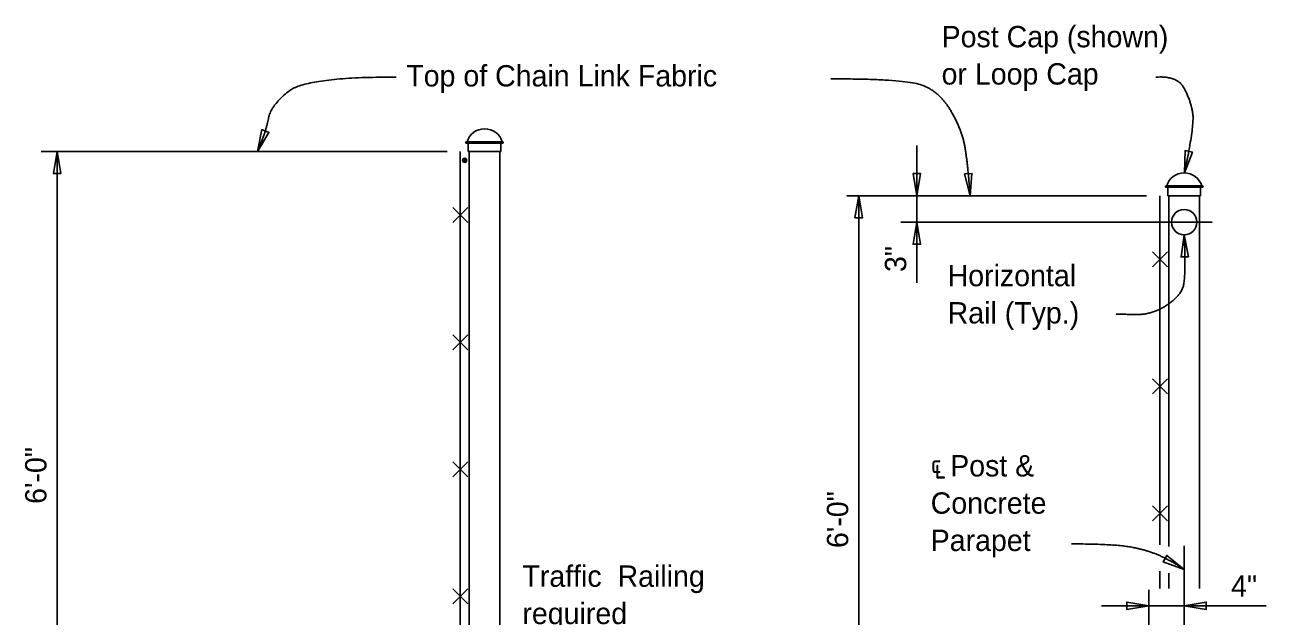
# Model space of a CAD drawing. Extents: x 0.2 to 40.8, y 0.5 to 25.7.
# Drawn here: x 29.1 to 40.83, y 18.84 to 24.42 of the extents above; entities that cross this region are included whole.
import ezdxf

# ---------------------------------------------------------------- set-up
doc = ezdxf.new("R2010")
doc.units = 0
for name, color, linetype in [('CL_Major', 7, 'Continuous'), ('Dimension', 7, 'Continuous'), ('Miscellaneous', 7, 'Continuous'), ('SteelMisc', 7, 'Continuous'), ('TextStructures', 7, 'Continuous')]:
    doc.layers.add(name, color=color, linetype=linetype)

msp = doc.modelspace()

# ---------------------------------------------------------------- linework, layer by layer
at = {"layer": 'CL_Major'}
for p, q in [((37.378, 22.558), (40.319, 22.558)), ((40.054, 15.283), (40.054, 19.502))]:
    msp.add_line(p, q, dxfattribs=at)
at = {"layer": 'Dimension'}
for p, q in [((33.092, 23.225), (29.256, 23.225)), ((29.406, 14.225), (29.406, 23.225)), ((37.528, 21.984), (37.528, 23.282)), ((39.699, 22.808), (36.866, 22.808)), ((36.98, 14.225), (36.98, 22.808)), ((39.72, 16.64), (39.72, 19.086)), ((39.274, 18.936), (40.828, 18.936))]:
    msp.add_line(p, q, dxfattribs=at)
for points in [[(31.3, 23.225), (31.408, 23.406), (31.342, 23.432)], [(29.406, 23.225), (29.371, 23.016), (29.441, 23.016)], [(40.057, 23.023), (40.131, 23.22), (40.062, 23.234)], [(37.528, 22.808), (37.563, 23.016), (37.492, 23.016)], [(38.031, 22.808), (38.049, 23.018), (37.979, 23.013)], [(36.98, 22.808), (36.944, 22.6), (37.015, 22.6)], [(37.528, 22.558), (37.492, 22.35), (37.563, 22.35)], [(40.054, 22.438), (40.024, 22.229), (40.095, 22.231)], [(40.054, 19.28), (39.889, 19.412), (39.855, 19.35)], [(39.72, 18.936), (39.512, 18.971), (39.512, 18.901)], [(40.054, 18.936), (40.262, 18.901), (40.262, 18.971)]]:
    msp.add_lwpolyline(points, close=True, dxfattribs=at)
for points in [[(32.608, 23.928), (31.76, 23.928), (31.424, 23.657), (31.383, 23.422), (31.3, 23.225)], [(39.786, 23.927), (39.992, 23.942), (40.118, 23.698), (40.152, 23.473), (40.057, 23.023)], [(36.717, 23.911), (37.4, 23.911), (37.736, 23.799), (37.958, 23.427), (38.014, 23.066), (38.031, 22.808)], [(39.41, 21.689), (39.436, 21.689), (39.754, 21.683), (40.017, 21.86), (40.072, 22.038), (40.054, 22.438)], [(38.988, 19.52), (39.396, 19.52), (39.727, 19.457), (39.975, 19.335), (40.054, 19.28)]]:
    msp.add_open_spline(points, degree=2, dxfattribs=at)
at = {"layer": 'Miscellaneous'}
for p, q in [((33.286, 22.695), (33.145, 22.554)), ((33.145, 22.695), (33.286, 22.554)), ((39.895, 22.279), (39.754, 22.137)), ((39.754, 22.279), (39.895, 22.137)), ((33.286, 21.495), (33.145, 21.354)), ((33.145, 21.495), (33.286, 21.354)), ((39.895, 21.079), (39.754, 20.937)), ((39.754, 21.079), (39.895, 20.937)), ((33.286, 20.295), (33.145, 20.154)), ((33.145, 20.295), (33.286, 20.154)), ((39.895, 19.879), (39.754, 19.737)), ((39.754, 19.879), (39.895, 19.737)), ((33.286, 19.095), (33.145, 18.954)), ((33.145, 19.095), (33.286, 18.954))]:
    msp.add_line(p, q, dxfattribs=at)
for points in [[(33.215, 23.225), (33.215, 17.225)], [(39.825, 22.808), (39.825, 19.51)], [(39.825, 19.262), (39.825, 19.1)]]:
    msp.add_lwpolyline(points, dxfattribs=at)
at = {"layer": 'SteelMisc'}
for p, q in [((33.215, 23.225), (33.215, 17.225)), ((33.272, 23.317), (33.617, 23.317)), ((33.617, 23.304), (33.272, 23.304)), ((33.291, 23.225), (33.291, 23.304)), ((33.599, 23.225), (33.291, 23.225)), ((33.299, 16.889), (33.299, 23.225)), ((33.59, 16.889), (33.59, 23.225)), ((33.599, 23.225), (33.599, 23.304)), ((39.881, 22.9), (40.226, 22.9)), ((40.226, 22.888), (39.881, 22.888)), ((39.9, 22.808), (39.9, 22.888)), ((40.208, 22.808), (40.208, 22.888)), ((40.208, 22.808), (39.9, 22.808)), ((39.908, 19.495), (39.908, 22.808)), ((40.2, 19.1), (40.2, 22.808)), ((39.908, 19.1), (39.908, 19.244))]:
    msp.add_line(p, q, dxfattribs=at)
for centre, radius in [((33.257, 23.141), 0.0197), ((33.257, 23.141), 0.0172), ((33.257, 23.141), 0.0147), ((33.257, 23.141), 0.0122), ((33.257, 23.141), 0.00975), ((33.257, 23.141), 0.00725), ((33.257, 23.141), 0.00475), ((33.257, 23.141), 0.00225), ((40.054, 22.558), 0.12)]:
    msp.add_circle(centre, radius, dxfattribs=at)
for centre, start, end in [((33.272, 23.31), 91.1647, 268.8353), ((33.617, 23.31), 271.1647, 88.8353), ((39.882, 22.894), 91.1647, 268.8353), ((40.226, 22.894), 271.1647, 88.8353)]:
    msp.add_arc(centre, 0.00613, start, end, dxfattribs=at)
for centre in [(33.445, 23.276), (40.054, 22.859)]:
    msp.add_ellipse(centre, major_axis=(0.171, 0), ratio=0.957868, start_param=0.252602, end_param=2.888574, dxfattribs=at)

# ---------------------------------------------------------------- texts
at = {"layer": 'Dimension'}
for s, p in [('Post Cap (shown) ', (37.762, 24.209)), ('or Loop Cap', (37.762, 23.857)), ('Horizontal', (37.819, 21.953)), ('Rail (Typ.)', (37.819, 21.601)), ('℄ Post &', (37.659, 20.157)), ('Concrete', (37.659, 19.805)), ('Parapet', (37.659, 19.453)), ('Traffic  Railing', (33.802, 19.115)), ('required', (33.802, 18.763))]:
    msp.add_text(s, height=0.2016, dxfattribs=at).set_placement(p)
at = {"layer": 'TextStructures'}
for s, p in [('Top of Chain Link Fabric', (32.705, 23.839)), ('4"', (40.497, 19.023))]:
    msp.add_text(s, height=0.2016, dxfattribs=at).set_placement(p)
for s, p in [('3"', (37.428, 22.087)), ('6\'-0"', (29.306, 19.898)), ('6\'-0"', (36.88, 19.481))]:
    msp.add_text(s, height=0.2016, rotation=90, dxfattribs=at).set_placement(p)

doc.saveas('drawing.dxf')
